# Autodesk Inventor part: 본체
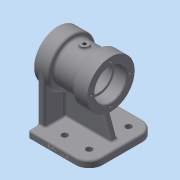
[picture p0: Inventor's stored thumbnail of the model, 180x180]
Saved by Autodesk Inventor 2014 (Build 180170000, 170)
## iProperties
Created: 2020-06
Part Number: 본체
Material: Generic
Document SubType Name: Modeling
Designer: kh
Density: 1 g/cm^3
Appearance: Default
Mass: 254.581 g
Surface Area: 616.877 cm^2
Volume: 254.581 cm^3
Author: kh
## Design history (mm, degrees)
sketch "Sketch1"
  geometry: L1 (-45, -49)-(45, -49); L2 (45, -49)-(45, 49); L3 (45, 49)-(-45, 49); L4 (-45, 49)-(-45, -49); L5 (-45, -49)-(45, 49); L6 (45, -49)-(-45, 49); 1 further point
  constraints: 12 end point, 2 midpoint, 2 parallel, 1 horizontal, 1 perpendicular
  dimensions: "d0" = 90 distance of L2.end L3.end; "d1" = 98 distance of L1.end L2.end
extrude "Extrusion1" new body sketch "Sketch1" distance "d2" = 10; taper "d3" = 0 deg
sketch "Sketch2"
  geometry: L1 (115.272, 80)-(-57.439, 80); L2 (50, 80)-(50, 115); L3 (50, 115)-(28, 115); L4 (28, 115)-(28, 109); L5 (28, 109)-(-6, 109); L6 (-6, 109)-(-6, 115); L7 (-6, 115)-(-28, 115); L8 (-28, 115)-(-28, 80); L9 (45, 0)-(45, 10) reference; L10 (50, 80)-(-28, 80); L11 (45, 0)-(-45, 0) reference; 1 further point
  constraints: 18 end point, 4 parallel, 3 perpendicular, 2 point on line, 1 collinear, 1 horizontal
  dimensions: "d4" = 5 distance between parallel lines of L9 L2; "d5" = 22 distance of L2.end L3.end; "d6" = 22 distance of L6.end L7.end; "d7" = 78 distance between parallel lines of L8 L2; "d8" = 70 diameter of L3 L1; "d9" = 58 diameter of L5 L1; "d10" = 70 diameter of L7 L1; "d94" = 80 distance between parallel lines of L11 L1
revolve "Revolution1" sketch "Sketch2" stored, may be unused: angle "d11" = 90 deg
workplane "Work Plane2"
  workplane "Work Plane1"
sketch "Sketch3"
  geometry: L1 (-39, 35)-(-39, -35) reference; C1 r 6 at (0, 0); 1 further point
  constraints: 1 centre point, 1 horizontal alignment
  dimensions: "d13" = 12 diameter of C1; "d14" = 39 distance from line of C1.centre L1
extrude "Extrusion2" join sketch "Sketch3" stored distance "d15" = 10; taper "d16" = 0 deg
sketch "Sketch4"
  geometry: L1 (-45, 49)-(-45, -49) reference; L2 (-45, 35)-(-35, 35); L3 (-35, 35)-(-35, -35); L4 (-35, -35)-(-45, -35); 2 further points
  constraints: 6 end point, 3 perpendicular, 2 point on line, 1 horizontal alignment, 1 midpoint
  dimensions: "d17" = 70 distance between parallel lines of L4 L2; "d18" = 10 distance of L2.start L2.end
extrude "Extrusion3" join sketch "Sketch4" stored distance "d19" = 10; taper "d20" = 0 deg
sketch "Sketch5"
  geometry: L1 (-28, 45)-(-28, 115) reference; L2 (-6, 45)-(-6, 115) reference; L3 (-45, 0)-(45, 0) reference; L4 (45, 0)-(45, 10) reference; L5 (-45, 10)-(45, 10) reference; L6 (-45, 0)-(-45, 10) reference; L7 (-12.102, 67.418)-(-33, 10); L8 (-12.102, 67.418)-(41.961, 67.418); L9 (41.961, 67.418)-(41.961, 10); L10 (41.961, 10)-(-33, 10); 1 further point
  constraints: 8 end point, 2 perpendicular, 2 point on line, 1 collinear
  dimensions: "d21" = 70 deg angle of L5 L7; "d22" = 12 distance from line of L6 L7.end
extrude "Extrusion4" join sketch "Sketch5" stored distance "d23" = 10; taper "d24" = 0 deg
sketch "Sketch6"
  geometry: L1 (50, 45)-(50, 115) reference; L2 (50, 103.5)-(32, 103.5); L3 (32, 103.5)-(32, 100); L4 (32, 100)-(26, 100); L5 (26, 100)-(26, 103); L6 (26, 103)-(-4, 103); L7 (-4, 103)-(-4, 100); L8 (-4, 100)-(-10, 100); L9 (-10, 100)-(-10, 103.5); L10 (-10, 103.5)-(-28, 103.5); L11 (-28, 45)-(-28, 115) reference; L12 (50, 80)-(-58.784, 80); L13 (50, 103.5)-(50, 80); L14 (50, 80)-(-28, 80); L15 (-28, 80)-(-28, 103.5); 1 further point
  constraints: 26 end point, 6 parallel, 3 perpendicular, 3 point on line, 2 collinear, 2 midpoint
  dimensions: "d34" = 18 distance of L2.start L2.end; "d35" = 6 distance of L3.end L4.end; "d36" = 30 distance of L5.end L6.end; "d37" = 18 distance of L9.end L10.end; "d39" = 47 diameter of L2 L12; "d40" = 40 diameter of L4 L12; "d41" = 46 diameter of L6 L12; "d42" = 40 diameter of L8 L12; "d43" = 47 diameter of L10 L12
revolve "Revolution2" sketch "Sketch6" stored, may be unused: angle "d44" = 90 deg
sketch "Sketch7"
  geometry: C1 r 23.5 at (0, 0) reference; 2 further points
  constraints: 1 horizontal alignment
  dimensions: "d45" = 28.5 distance of C1.centre point (-28.5, 0)
hole "Hole1" sketch "Sketch7" at (-28.5, 0) diameter "d46" = 3.242; stored, may be unused: countersink angle "d50" = 90 deg, drill point angle "d52" = 118 deg; dims "d47" = 10, "d48" = 4, "d49" = 2, "d51" = 12
pattern_circular "Circular Pattern1" dims angle "d54" = 360 deg
workplane "Work Plane3"
mirror "Mirror1"
hole "Hole2" diameter "d58" = 5.188; stored, may be unused: countersink angle "d62" = 90 deg, drill point angle "d64" = 118 deg; dims "d56" = 10, "d57" = 10, "d59" = 10, "d60" = 4, "d61" = 2, "d63" = 12
sketch "Sketch8"
  geometry: L1 (-45, 49)-(-45, 35) reference; 2 further points
  dimensions: "d65" = 70 distance from line of point (25, 29) L1; "d66" = 29 vertical distance of point (0, 0) point (25, 29)
hole "Hole3" sketch "Sketch8" at (25, 29) diameter "d67" = 9; stored, may be unused: countersink angle "d71" = 90 deg, drill point angle "d73" = 0 deg; dims "d68" = 10, "d69" = 4, "d70" = 2, "d72" = 12
pattern_linear "Rectangular Pattern1" dims "d76" = 58, "d79" = 36
chamfer "Chamfer1" distance "d80" = 1; stored, may be unused: second distance "d81" = 2, angle "d82" = 45 deg
fillet "Fillet1" dims "d83" = 20
fillet "Fillet3" dims "d85" = 3
fillet "Fillet4" dims "d86" = 3
fillet "Fillet5" dims "d87" = 3
fillet "Fillet6" dims "d88" = 3
sketch "Sketch9"
  geometry: L1 (0, 0)-(67, 0) reference; L2 (-3, 7)-(-3, 0) reference; 2 further points
  constraints: 1 other
  dimensions: "d90" = 45 distance from line of point (42, 4) L2; "d91" = 4 distance from line of L1 point (42, 4)
emboss "Emboss1" sketch "Sketch9" dims "d0" = 90, "d1" = 98, "d92" = 0.5, "d93" = 0
fillet "Fillet8" dims "d95" = 3
fillet "Fillet9" dims "d96" = 0.3
fillet "Fillet10" dims "d97" = 3
body "Solid1"
node "Projected Loop1"
node "Projected Loop2"
other parameters: "d12" = 3
